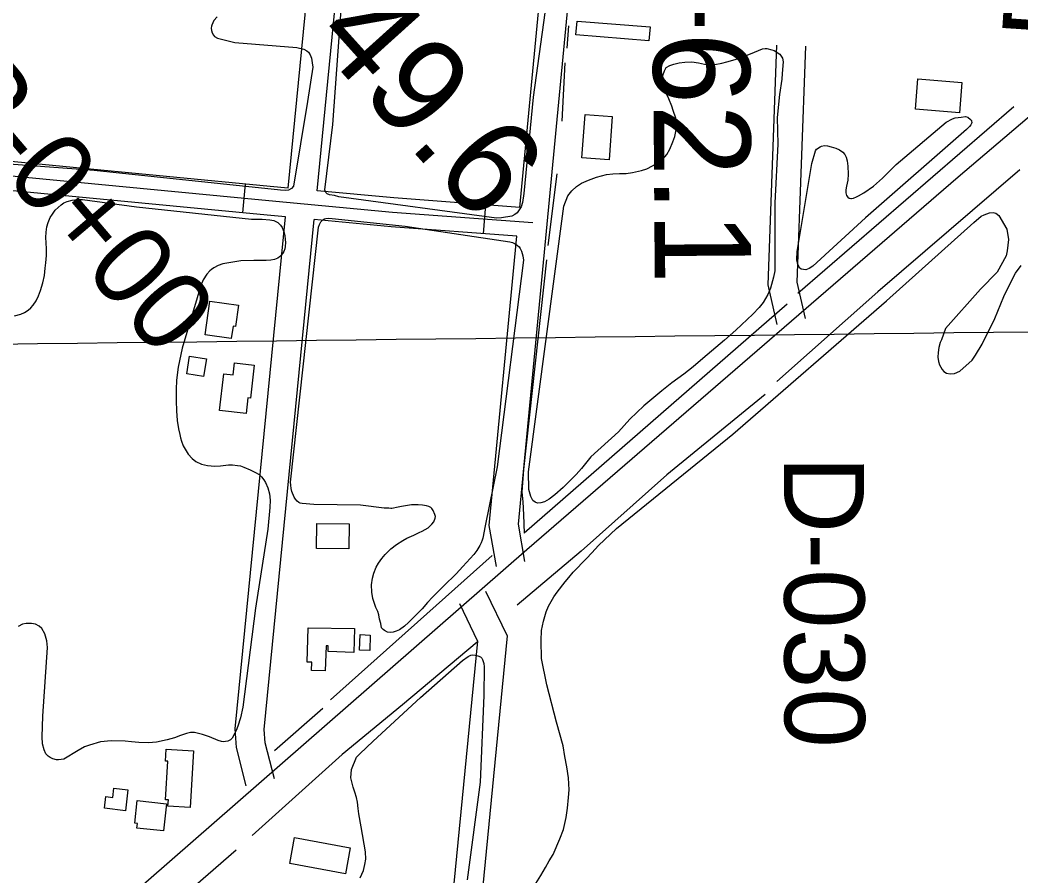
# Model space of a CAD drawing. Extents: x 3704301 to 3742427, y 506229 to 532009.
# Drawn here: x 3714502 to 3715539, y 517227 to 518113 of the extents above; entities that cross this region are included whole.
import ezdxf

# ---------------------------------------------------------------- set-up
doc = ezdxf.new("R2010")
doc.units = 0
for name, color, linetype in [('V-BLDG-OTLN', 7, 'Continuous'), ('V-GRID-MAJR', 7, 'Continuous'), ('V-RIVR-RANG-IDEN', 7, 'Continuous'), ('V-ROAD-CNTR', 7, 'Continuous'), ('V-SITE-VEGE', 7, 'Continuous'), ('V-SURV-IDEN', 7, 'Continuous'), ('V-TOPO-SHOR', 7, 'Continuous')]:
    doc.layers.add(name, color=color, linetype=linetype)

msp = doc.modelspace()

# ---------------------------------------------------------------- linework, layer by layer
at = {"layer": 'V-BLDG-OTLN'}
for points in [[(3715079.161, 518112.01300000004), (3715154.7, 518105.896), (3715153.549, 518091.673), (3715078.0100000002, 518097.794)], [(3715431.94, 518052.13800000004), (3715477.465, 518048.501), (3715474.958, 518017.099), (3715429.431, 518020.734)], [(3715115.519, 518013.289), (3715112.224, 517968.434), (3715084.085, 517970.503), (3715087.382, 518015.356)], [(3714694.051, 517787.293), (3714698.938, 517822.00800000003), (3714728.722, 517817.816), (3714725.629, 517795.835), (3714722.879, 517796.222), (3714721.085, 517783.49)], [(3714677.981, 517765.172), (3714695.333, 517762.30700000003), (3714692.319, 517744.041), (3714674.966, 517746.90400000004)], [(3714709.002, 517708.856), (3714713.2430000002, 517746.951), (3714723.1350000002, 517745.851), (3714724.503, 517758.13300000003), (3714744.772, 517755.876), (3714740.961, 517721.65400000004), (3714738.19, 517721.961), (3714736.392, 517705.80700000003)], [(3714809.642, 517591.977), (3714843.219, 517591.657), (3714842.974, 517565.842), (3714809.399, 517566.164)], [(3714800.545, 517484.121), (3714848.628, 517483.202), (3714848.153, 517458.337), (3714821.271, 517459.596), (3714821.539, 517465.341), (3714819.434, 517465.228), (3714818.3200000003, 517439.456), (3714804.3140000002, 517439.749), (3714804.5270000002, 517448.445), (3714799.744, 517448.56200000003)], [(3714865.074, 517476.369), (3714864.416, 517460.346), (3714853.795, 517460.78), (3714854.463, 517477.06200000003)], [(3714682.122, 517356.588), (3714678.472, 517298.01300000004), (3714655.526, 517299.445), (3714655.93, 517305.902), (3714653.018, 517306.08400000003), (3714655.498, 517345.87700000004), (3714652.981, 517346.03500000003), (3714653.7490000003, 517358.35500000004)], [(3714614.009, 517316.408), (3714611.4820000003, 517294.63), (3714589.753, 517297.151), (3714591.17, 517309.371), (3714598.5100000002, 517308.521), (3714599.6180000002, 517318.079)], [(3714623.801, 517305.181), (3714654.078, 517301.958), (3714651.076, 517273.78500000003), (3714623.451, 517276.728), (3714623.9560000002, 517281.48000000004), (3714621.306, 517281.77)], [(3714786.48, 517266.865), (3714844.09, 517256.363), (3714839.1950000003, 517229.512), (3714781.5870000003, 517240.02400000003)]]:
    msp.add_lwpolyline(points, close=True, dxfattribs=at)
at = {"layer": 'V-GRID-MAJR'}
msp.add_spline([(3708498.534, 517706.704), (3713778.102, 517769.291), (3719057.661, 517832.646), (3724337.211, 517896.76900000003), (3729616.752, 517961.659), (3734896.2830000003, 518027.318), (3740175.804, 518093.744), (3740175.805, 518093.744)], degree=3, dxfattribs=at)
at = {"layer": 'V-ROAD-CNTR'}
for p, q in [((3714732.92849517, 517913.5131467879), (3714735.795489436, 517943.3760870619)), ((3714982.283996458, 517891.80519020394), (3714984.533991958, 517921.7211303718))]:
    msp.add_line(p, q, dxfattribs=at)
for points in [[(3715025.146910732, 517552.5738686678), (3715018.4699240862, 517591.2037914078), (3715099.763761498, 518439.907093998)], [(3715019.73792155, 517919.07213566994), (3715069.2978224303, 518436.48110084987)], [(3714809.9053412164, 517936.355101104), (3714856.3122484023, 518410.294153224)], [(3716017.174926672, 518412.61314858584), (3715473.6600137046, 517950.299073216)], [(3714780.0354009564, 517939.165095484), (3714825.8863092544, 518407.404159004)], [(3715286.2113886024, 517797.7743782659), (3715277.026406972, 517838.8792960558), (3715285.970389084, 518087.17179947)], [(3715315.4893300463, 517804.31636518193), (3715307.146346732, 517841.655290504), (3715315.950329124, 518086.09180163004)], [(3715033.26789449, 517903.01216779), (3714888.08318486, 517913.93414594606), (3714759.820441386, 517926.00112181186), (3714342.0352769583, 517966.1060416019), (3714115.0197309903, 517989.353995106), (3714102.3587563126, 517990.215993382), (3714096.372768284, 517989.7229943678), (3714088.4417841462, 517986.47200087), (3714083.021794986, 517981.5450107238), (3714078.6258037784, 517970.86603208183), (3714051.177858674, 517710.09155363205)], [(3714780.0354009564, 517939.165095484), (3714761.239438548, 517940.9340919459), (3714331.6192977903, 517982.17500946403)], [(3715473.6600137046, 517950.299073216), (3715027.19790663, 517564.69484442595), (3714357.4142462, 516980.69801242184), (3713747.034466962, 516446.77508026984), (3713270.6784196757, 516033.2769072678), (3712868.5772238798, 515682.3716090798), (3712145.2626705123, 515057.3558591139), (3711578.9428031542, 514561.52985076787), (3711154.4176522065, 514191.46559089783), (3710803.5753538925, 513881.8562101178)], [(3714777.1134068, 517909.3081551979), (3714758.4014442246, 517911.06815167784), (3714328.740303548, 517952.31306918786)], [(3715019.73792155, 517919.07213566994), (3714889.3481823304, 517928.8811160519), (3714809.9053412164, 517936.355101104)], [(3714736.6804876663, 517320.31233319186), (3714726.4125082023, 517360.1882534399), (3714725.229510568, 517379.45221491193), (3714777.1134068, 517909.3081551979)], [(3714765.732429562, 517327.79231823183), (3714756.180448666, 517364.890244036), (3714755.319450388, 517378.90621600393), (3714806.981347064, 517906.49716082)], [(3715016.876927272, 517889.20219541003), (3714886.8181873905, 517898.9871758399), (3714806.981347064, 517906.49716082)], [(3714995.5849698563, 517547.4638788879), (3714988.223984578, 517590.0597936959), (3715016.876927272, 517889.20219541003)], [(3714984.3059924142, 517522.0209297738), (3715006.6029478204, 517475.72402236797), (3714969.674021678, 517096.36278109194)], [(3714957.27804647, 517509.004955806), (3714975.931009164, 517470.272033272), (3714939.8160813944, 517099.26877528)]]:
    msp.add_lwpolyline(points, dxfattribs=at)
at = {"layer": 'V-SITE-VEGE'}
for points in [[(3715080.665, 518372.83), (3715033.714, 518033.413), (3715024.0500000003, 517933.528), (3715022.5530000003, 517924.12200000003), (3715021.387, 517919.634), (3715016.97, 517913.488), (3715014.703, 517911.82300000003), (3715011.594, 517910.164), (3715001.0300000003, 517908.297), (3714995.543, 517908.06700000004), (3714832.361, 517930.145), (3714827.8740000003, 517931.451), (3714822.9590000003, 517932.06200000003), (3714820.296, 517933.071), (3714818.906, 517934.49100000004), (3714818.086, 517937.452), (3714826.319, 518004.868), (3714853.687, 518384.686)], [(3714706.593, 518116.525), (3714703.183, 518112.761), (3714700.8850000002, 518107.862), (3714700.453, 518106.60000000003), (3714700.435, 518104.632), (3714700.691, 518102.099), (3714701.375, 518099.983), (3714702.616, 518097.44), (3714703.7260000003, 518096.022), (3714706.804, 518094.306), (3714724.759, 518089.917), (3714789.111, 518084.666), (3714796.126, 518082.77400000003), (3714799.345, 518081.336), (3714801.16, 518079.772), (3714802.683, 518077.228), (3714804.051, 518073.558), (3714804.989, 518068.626), (3714805.37, 518064.264), (3714799.97, 518028.60000000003), (3714785.503, 517941.276), (3714783.369, 517938.765), (3714780.2600000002, 517937.108), (3714777.302, 517936.715), (3714771.961, 517936.905), (3714579.234, 517957.434), (3714448.971, 517966.88800000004)], [(3714496.757, 517806.994), (3714503.239, 517808.621), (3714506.911, 517810.271), (3714510.944, 517812.907), (3714513.639, 517815.34), (3714515.842, 517817.851), (3714519.119, 517822.389), (3714521.628, 517827.569), (3714523.719, 517833.033), (3714526.048, 517841.16500000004), (3714527.594, 517848.604), (3714528.44, 517856.331), (3714529.1950000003, 517861.805), (3714529.617, 517869.256), (3714529.685, 517876.286), (3714529.253, 517882.617), (3714529.163, 517887.96), (3714529.427, 517893.653), (3714530.252, 517899.199), (3714531.631, 517903.476), (3714533.717, 517908.731), (3714535.862, 517912.292), (3714538.852, 517916.272), (3714541.69, 517919.059), (3714545.09, 517921.908), (3714547.8510000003, 517923.71), (3714551.168, 517925.156), (3714556.315, 517926.651), (3714561.736, 517927.374), (3714567.077, 517927.255), (3714623.051, 517919.819), (3714742.114, 517907.06200000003), (3714748.088, 517906.863), (3714752.937, 517906.88800000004), (3714761.088, 517906.39), (3714765.1580000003, 517905.507), (3714767.4, 517904.713), (3714769.43, 517903.568), (3714770.823, 517902.218), (3714772.074, 517900.729), (3714773.948, 517898.18200000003), (3714775.865, 517892.75), (3714776.401, 517890.143), (3714776.9930000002, 517885.849), (3714777.106, 517882.754), (3714776.856, 517878.75), (3714776.481, 517876.293), (3714775.613, 517873.558), (3714774.468, 517871.67), (3714772.549, 517869.368), (3714770.988, 517867.908), (3714769.149, 517866.661), (3714765.762, 517865.287), (3714761.8850000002, 517864.408), (3714757.173, 517864.173), (3714751.057, 517864.23000000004), (3714744.588, 517864.15), (3714731.085, 517863.716), (3714718.41, 517861.727), (3714712.356, 517860.591), (3714707.558, 517858.876), (3714703.105, 517856.599)], [(3715036.458, 517219.31700000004), (3715041.46, 517227.705), (3715046.3170000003, 517235.815), (3715050.18, 517242.809), (3715054.46, 517249.238), (3715061.223, 517265.485), (3715065.253, 517275.289), (3715067.7600000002, 517287.63800000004), (3715069.1180000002, 517297.327), (3715070.207, 517308.425), (3715071.125, 517316.435), (3715070.117, 517328.67600000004), (3715068.399, 517340.22000000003), (3715066.531, 517350.925), (3715064.807, 517361.76900000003), (3715057.87, 517386.44200000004), (3715047.97, 517424.924), (3715042.465, 517452.254), (3715041.798, 517470.963), (3715042.318, 517481.223), (3715043.2090000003, 517486.134), (3715044.239, 517491.045), (3715047.004, 517500.583), (3715049.727, 517506.461), (3715055.021, 517515.974), (3715058.585, 517521.001), (3715066.98, 517531.467), (3715070.537, 517536.075), (3715075.09, 517541.514), (3715089.006, 517555.867), (3715094.2630000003, 517561.722), (3715101.366, 517569.107), (3715120.095, 517586.927), (3715240.398, 517684.354), (3715399.475, 517822.473), (3715489.898, 517903.67600000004), (3715497.691, 517909.931), (3715500.801, 517911.588), (3715506.022, 517913.507), (3715509.823, 517913.89400000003), (3715512.907, 517913.01900000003), (3715515.838, 517910.742), (3715523.9990000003, 517896.60500000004), (3715525.867, 517885.75800000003), (3715524.63, 517874.099), (3715523.4560000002, 517868.91000000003), (3715514.156, 517852.12200000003), (3715496.8340000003, 517834.429), (3715460.593, 517793.856), (3715456.407, 517782.226), (3715455.115, 517779.424), (3715453.8000000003, 517774.235), (3715452.907, 517769.041), (3715452.721, 517764.261), (3715453.38, 517759.755), (3715454.472, 517756.08900000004), (3715457.093, 517751.283), (3715458.9080000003, 517749.43700000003), (3715461.701, 517747.58400000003), (3715465.3510000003, 517746.847), (3715469.8540000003, 517747.367), (3715475.503, 517749.704), (3715488.1240000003, 517761.113), (3715491.5470000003, 517766.143), (3715498.5470000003, 517777.74700000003), (3715511.592, 517804.199), (3715520.948, 517826.889), (3715524.679, 517834.728), (3715532.99, 517851.10000000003), (3715538.968, 517858.919)], [(3714703.105, 517856.599), (3714700.488, 517854.86600000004), (3714698.9990000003, 517853.615), (3714695.872, 517849.918), (3714692.091, 517844.329), (3714689.646, 517838.44800000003), (3714685.867, 517825.408), (3714670.116, 517773.31700000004), (3714666.063, 517753.81), (3714664.251, 517740.471), (3714663.946, 517730.631), (3714663.974, 517718.82), (3714664.23, 517708.694), (3714665.1210000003, 517698.7), (3714666.583, 517689.97000000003), (3714667.722, 517684.053), (3714668.605, 517680.67), (3714669.557, 517677.286), (3714671.269, 517672.488), (3714676.529, 517663.72000000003), (3714680.6350000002, 517659.25), (3714684.399, 517655.983), (3714690.42, 517653.253), (3714696.525, 517651.93), (3714703.972, 517651.228), (3714709.811, 517651.594), (3714718.187, 517652.639), (3714722.265, 517652.67100000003), (3714727.602, 517652.129), (3714730.549, 517651.537), (3714734.055, 517650.38), (3714740.772, 517647.363), (3714746.234, 517644.781), (3714749.802, 517642.847), (3714752.518, 517640.15), (3714754.949, 517637.033), (3714756.612, 517634.55700000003), (3714758.879, 517628.841), (3714760.509, 517622.70900000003), (3714761.4280000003, 517616.09), (3714761.004, 517608.363), (3714758.823, 517586.025), (3714746.097, 517504.308), (3714733.103, 517401.927), (3714730.536, 517390.702), (3714727.784, 517382.221), (3714726.125, 517377.87700000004), (3714724.759, 517374.86600000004), (3714722.111, 517369.689), (3714720.196, 517368.02), (3714717.585, 517366.781), (3714715.187, 517366.24), (3714712.795, 517365.982), (3714710.898, 517366.21), (3714707.394, 517367.297), (3714698.502, 517371.039), (3714695.278, 517372.26300000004), (3714691.3540000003, 517373.568), (3714683.004, 517375.47500000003), (3714679.001, 517375.722), (3714674.56, 517374.639), (3714668.4250000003, 517372.51900000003), (3714662.143, 517370.047), (3714654.883, 517368.14900000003), (3714643.681, 517365.511), (3714635.45, 517364.886), (3714625.396, 517365.194), (3714617.952, 517365.896), (3714611.279, 517366.734), (3714596.661, 517367.08400000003), (3714585.54, 517365.992), (3714574.3310000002, 517362.65400000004), (3714569.109, 517360.666), (3714562.467, 517357.071), (3714547.761, 517348.142), (3714542.34, 517347.349), (3714540.16, 517347.37200000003), (3714536.4450000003, 517348.531), (3714533.644, 517349.68200000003), (3714531.336, 517350.97000000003), (3714529.251, 517353.52), (3714527.322, 517357.614), (3714525.691, 517363.819), (3714525.409, 517370.994), (3714525.829, 517392.713), (3714530.645, 517463.537), (3714530.148, 517470.36100000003), (3714528.036, 517477.623), (3714524.995, 517483.136), (3714522.068, 517485.766), (3714518.429, 517487.62700000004), (3714514.29, 517488.51), (3714508.875, 517488.49100000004), (3714504.861, 517487.68700000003), (3714500.341, 517485.479)], [(3714854.41, 517225.268), (3714856.163, 517228.895), (3714857.848, 517232.934), (3714859.421, 517239.174), (3714860.298, 517244.39), (3714860.025, 517252.228), (3714855.737, 517278.113), (3714853.111, 517291.33900000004), (3714852.548, 517297.049), (3714851.649, 517303.518), (3714850.594, 517308.476), (3714849.132, 517313.715), (3714847.186, 517318.88800000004), (3714844.944, 517328.739), (3714845.437, 517337.259), (3714850.85, 517349.99100000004), (3714854.113, 517353.397), (3714867.8510000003, 517366.742), (3714917.083, 517411.984), (3714960.4760000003, 517450.202), (3714966.4250000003, 517454.409), (3714969.12, 517455.82800000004), (3714970.703, 517456.086), (3714973.589, 517455.853), (3714976.3310000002, 517455.068), (3714979.0670000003, 517453.809), (3714980.431, 517452.49), (3714981.38, 517451.10500000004), (3714982.717, 517447.173), (3714982.9560000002, 517443.46), (3714982.608, 517414.045), (3714978.666, 517324.309), (3714965.3310000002, 517222.979)]]:
    msp.add_lwpolyline(points, dxfattribs=at)
for points in [[(3715242.946, 518072.37), (3715258.632, 518078.20300000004), (3715271.0300000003, 518083.294), (3715273.734, 518083.462), (3715275.468, 518083.446), (3715280.861, 518082.237), (3715283.361, 518081.443), (3715284.127, 518080.853), (3715289.116, 518077.914), (3715291.778, 518073.64400000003), (3715292.7060000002, 518069.775), (3715291.629, 518057.821), (3715290.992, 518052.04000000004), (3715288.719, 518035.852), (3715286.37, 518012.141), (3715286.882, 517984.542), (3715283.7970000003, 517923.98000000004), (3715283.994, 517863.38800000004), (3715283.9020000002, 517853.547), (3715282.487, 517846.808), (3715279.486, 517835.64400000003), (3715276.722, 517828.916), (3715271.821, 517820.667), (3715267.721, 517815.686), (3715261.288, 517808.803), (3715243.3740000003, 517791.99100000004), (3715231.7, 517781.876), (3715209.523, 517762.786), (3715199.213, 517754.20300000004), (3715189.686, 517746.574), (3715177.25, 517737.43), (3715166.947, 517729.424), (3715148.271, 517713.585), (3715133.863, 517700.021), (3715121.969, 517687.012), (3715093.356, 517660.847), (3715083.595, 517648.977), (3715078.133, 517642.853), (3715064.883, 517629.087), (3715056.125, 517621.64400000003), (3715050.299, 517617.262), (3715045.4450000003, 517614.22000000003), (3715041.771, 517613.29000000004), (3715038.1010000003, 517612.938), (3715035.795, 517613.925), (3715033.495, 517615.685), (3715031.22, 517619.951), (3715029.358, 517627.108), (3715028.953, 517645.44200000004), (3715065.522, 517920.261), (3715069.484, 517931.222), (3715073.585, 517936.201), (3715078.453, 517940.788), (3715083.886, 517944.208), (3715090.864, 517947.422), (3715099.191, 517950.43), (3715109.443, 517953.033), (3715116.009, 517953.744), (3715122.96, 517954.063), (3715130.099, 517954.188), (3715136.673, 517955.286), (3715145.955, 517957.512), (3715151.372, 517959.19800000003), (3715157.383, 517962.034), (3715163.9790000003, 517965.831), (3715167.4790000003, 517968.69200000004), (3715171.968, 517974.054), (3715175.301, 517979.42600000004), (3715178.4590000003, 517986.917), (3715180.443, 517992.691), (3715181.856, 517999.431), (3715182.2970000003, 518005.022), (3715181.3910000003, 518011.39900000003), (3715178.768, 518019.528), (3715177.265, 518023.787), (3715174.25, 518031.53500000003), (3715171.219, 518037.351), (3715169.148, 518042.967), (3715168.057, 518049.924), (3715167.92, 518055.71400000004), (3715169.509, 518060.525), (3715171.469, 518063.787), (3715175.348, 518066.064), (3715179.417, 518067.57), (3715185.024, 518068.868), (3715190.628, 518069.587), (3715197.9620000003, 518069.71), (3715204.708, 518068.87200000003), (3715211.059, 518067.26900000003), (3715217.424, 518066.822), (3715221.669, 518066.976), (3715229.015, 518068.45), (3715234.045, 518069.753)], [(3715325.89, 517977.61100000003), (3715326.967, 517979.436), (3715330.754, 517981.906), (3715332.208, 517982.664), (3715335.301, 517983.118), (3715338.577, 517982.701), (3715342.235, 517981.89400000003), (3715347.238, 517980.39900000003), (3715350.792, 517978.631), (3715354.339, 517976.186), (3715356.534, 517973.847), (3715357.859, 517971.03500000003), (3715358.8850000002, 517967.265), (3715359.6040000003, 517961.75800000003), (3715359.911, 517953.553), (3715359.3710000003, 517947.479), (3715357.9620000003, 517941.222), (3715357.441, 517937.17600000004), (3715357.413, 517934.087), (3715358.255, 517931.38), (3715359.395, 517929.631), (3715361.028, 517928.652), (3715362.664, 517928.248), (3715363.2430000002, 517928.43700000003), (3715365.273, 517928.803), (3715368.566, 517930.12200000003), (3715370.506, 517931.167), (3715376.129, 517934.392), (3715386.038, 517941.24700000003), (3715395.475, 517949.357), (3715409.504, 517963.695), (3715461.148, 518007.492), (3715467.7430000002, 518010.70900000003), (3715470.5500000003, 518011.83900000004), (3715476.926, 518012.648), (3715481.274, 518013.185), (3715483.8710000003, 518012.38800000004), (3715486.359, 518010.242), (3715487.4080000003, 518008.978), (3715487.688, 518008.303), (3715487.872, 518007.141), (3715487.569, 518005.98600000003), (3715486.98, 518004.544), (3715485.613, 518002.82), (3715482.208, 517999.766), (3715377.721, 517908.52), (3715323.41, 517858.479), (3715319.429, 517855.913), (3715316.039, 517854.69), (3715311.318, 517855.219), (3715309.688, 517856.39), (3715307.796, 517860.17100000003), (3715306.684, 517865.006), (3715306.9560000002, 517873.58900000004), (3715322.099, 517964.623)], [(3714914.566, 517611.22000000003), (3714907.674, 517611.216), (3714897.256, 517609.62700000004), (3714893.9420000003, 517608.744), (3714887.46, 517607.54000000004), (3714886.197, 517607.48000000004), (3714884.372, 517607.77900000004), (3714879.4280000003, 517607.773), (3714854.776, 517610.88800000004), (3714806.486, 517611.76900000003), (3714794.3340000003, 517612.588), (3714792.435, 517612.887), (3714790.967, 517613.604), (3714789.1520000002, 517615.097), (3714787.485, 517617.081), (3714786.377, 517619.06200000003), (3714783.903, 517625.06), (3714783.162, 517628.231), (3714782.631, 517631.68200000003), (3714782.449, 517634.848), (3714811.3200000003, 517898.786), (3714812.399, 517901.587), (3714813.691, 517904.31700000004), (3714815.8170000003, 517906.124), (3714817.585, 517907.162), (3714819.137, 517907.57), (3714821.248, 517907.901), (3714825.6720000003, 517907.647), (3714901.247, 517899.55), (3715009.58, 517883.61600000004), (3715012.384, 517882.818), (3715015.112, 517881.454), (3715017.488, 517879.746), (3715019.161, 517878.183), (3715020.199, 517876.555), (3715021.44, 517874.011), (3715022.401, 517871.472), (3715023.011, 517869.145), (3715023.81, 517864.359), (3714996.2830000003, 517650.591), (3714984.1010000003, 517589.398), (3714981.523, 517576.908), (3714980.802, 517574.735), (3714979.717, 517571.794), (3714978.498, 517569.273), (3714975.424, 517563.958), (3714972.153, 517559.911), (3714960.852, 517547.294), (3714954.1040000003, 517539.90400000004), (3714941.0500000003, 517527.44200000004), (3714936.432, 517522.566), (3714929.6180000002, 517515.67), (3714924.294, 517510.098), (3714918.6780000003, 517503.751), (3714904.623, 517489.472), (3714900.369, 517485.786), (3714895.271, 517482.038), (3714891.952, 517480.45300000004), (3714888.7770000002, 517479.429), (3714885.963, 517479.173), (3714882.875, 517479.626), (3714879.864, 517481.059), (3714878.47, 517482.268), (3714876.798, 517483.972), (3714875.787, 517488.34), (3714874.5640000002, 517492.92100000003), (3714873.761, 517497.359), (3714872.811, 517500.743), (3714870.742, 517505.052), (3714867.666, 517514.503), (3714866.4620000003, 517520.981), (3714866.186, 517528.647), (3714867.161, 517535.245), (3714868.617, 517540.507), (3714871.1380000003, 517546.737), (3714873.497, 517550.863), (3714876.848, 517555.824), (3714880.401, 517559.868), (3714886.148, 517565.57800000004), (3714892.24, 517570.303), (3714898.821, 517574.528), (3714902.99, 517576.809), (3714910.119, 517579.906), (3714915.489, 517582.59500000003), (3714918.596, 517583.973), (3714921.985, 517585.628), (3714924.887, 517587.57), (3714927.085, 517589.44800000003), (3714928.859, 517591.25800000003), (3714930.849, 517593.841), (3714932.154, 517597.554), (3714932.449, 517599.167), (3714931.978, 517601.281), (3714930.259, 517605.447), (3714928.875, 517607.63800000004), (3714927.687, 517608.63300000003), (3714925.588, 517609.56700000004), (3714923.132, 517610.155), (3714919.063, 517610.896)]]:
    msp.add_lwpolyline(points, close=True, dxfattribs=at)
at = {"layer": 'V-TOPO-SHOR'}
for p, q in [((3715070.197, 518106.981), (3715068.661, 518083.878)), ((3715066.6380000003, 518068.67100000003), (3715063.248, 518008.559)), ((3715531.4050000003, 518023.29000000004), (3715307.7800000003, 517829.93200000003)), ((3715058.0300000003, 517953.912), (3715048.722, 517879.688)), ((3715296.776, 517819.135), (3715024.24, 517581.884)), ((3714991.318, 517558.889), (3714823.745, 517409.36100000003)), ((3714975.715, 517469.265), (3714898.458, 517404.42100000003)), ((3714815.7660000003, 517400.413), (3714765.727, 517356.531)), ((3714726.0100000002, 517253.94), (3714633.207, 517173.435))]:
    msp.add_line(p, q, dxfattribs=at)
for points in [[(3715537.471, 517958.09), (3715390.41, 517831.771), (3715285.9420000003, 517738.86600000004)], [(3715047.6410000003, 517864.848), (3715023.7770000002, 517647.795), (3715022.057, 517624.88), (3715022.897, 517614.347), (3715023.71, 517600.806), (3715024.24, 517581.884)], [(3715273.994, 517725.64400000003), (3715172.022, 517642.27), (3715083.218, 517563.309), (3715017.045, 517507.571)], [(3714898.458, 517404.42100000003), (3714836.039, 517352.719), (3714742.583, 517269.042)]]:
    msp.add_lwpolyline(points, dxfattribs=at)

# ---------------------------------------------------------------- texts
at = {"layer": 'V-RIVR-RANG-IDEN'}
for s, height, rotation, p in [('R-87.9', 82.99999799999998, 86.26736459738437, (3715601.697, 518090.401)), ('R-0+00', 82.99999799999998, 310.4046315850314, (3714409.287, 518041.153)), ('D-030', 83, 270.1753257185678, (3715293.2357870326, 517661.8874078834))]:
    msp.add_text(s, height=height, rotation=rotation, dxfattribs=at).set_placement(p)
at = {"layer": 'V-SURV-IDEN'}
for s, height, rotation, p in [('418+62.1', 100.00000000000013, 270.3945901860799, (3715155.744842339, 518401.245214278)), ('413+49.6', 99.99999999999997, 312.0261233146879, (3714602.1475829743, 518317.5969287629))]:
    msp.add_text(s, height=height, rotation=rotation, dxfattribs=at).set_placement(p)

doc.saveas('drawing.dxf')
